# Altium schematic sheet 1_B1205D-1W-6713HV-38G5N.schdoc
size 289 x 200 mm; Name: default297x210; Symbol: default297x210; Device: default297x210; Date: 2025.07.04; Rev: V1.1; Size: "A4"; Id: /; File: B1205D-1W-6713HV-38G5N; Sheet: /; @Page No: 1; @Page Count: 1; @Schematic Name: B1205D-1W-6713HV-38G5N; @Project Name: 全桥隔离电源-B1205D-1W-6713HV-38G5N; @Board Name: B1205D-1W-6713HV-38G5N; @Update Date: 2025-06-24; @Create Time: 13:56:28; @Update Time: 17:11:45; @Page Name: B1205D-1W-6713HV-38G5N; @Create Date: 2025-06-24
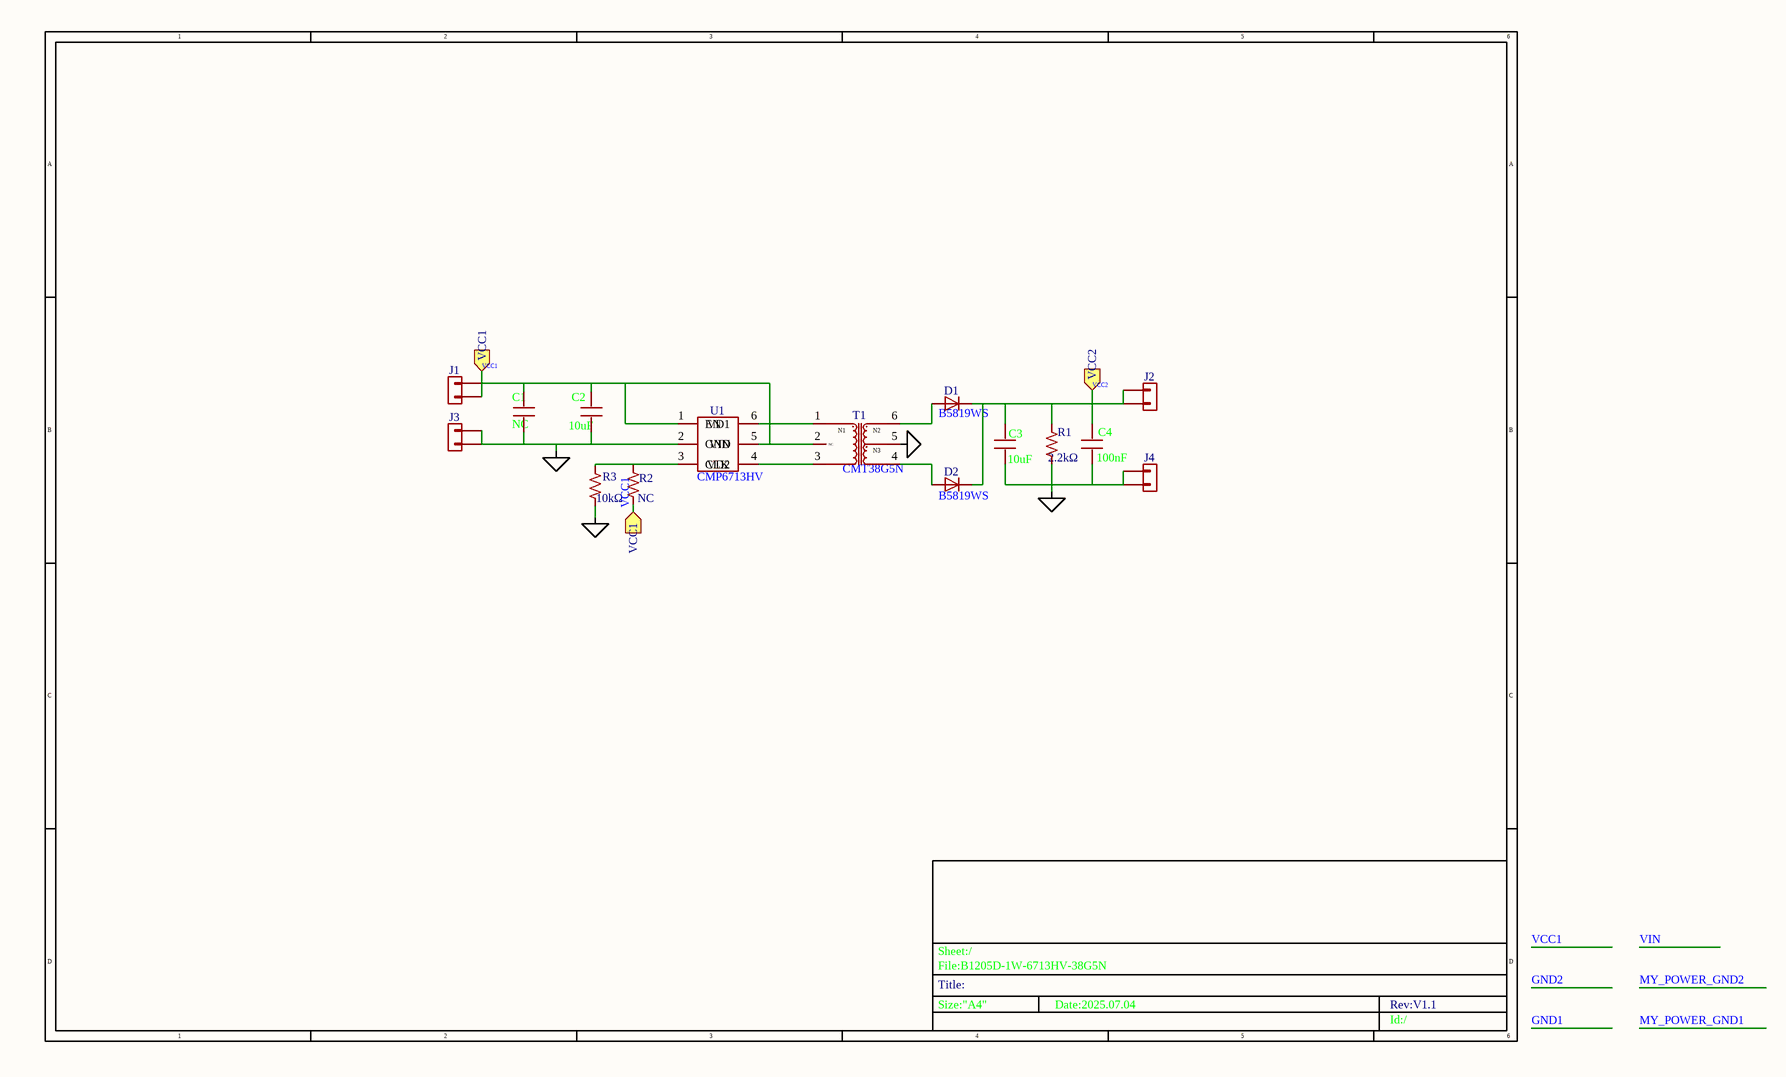
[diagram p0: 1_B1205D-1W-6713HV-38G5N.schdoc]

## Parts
C1  NC  [C0603]
C2  10uF  [C0603]
C3  10uF  [C0603]
C4  100nF  [C0603]
D1  B5819WS  [SOD-323_L1.8-W1.3-LS2.5-RD]
D2  B5819WS  [SOD-323_L1.8-W1.3-LS2.5-RD]
J1  Connector_Generic_Conn_01x02  [Connector_PinHeader_2.54mm:PinHeader_1x02_P2.54mm_Vertical_SMD_Pin1Right]  (value not drawn)
J2  Connector_Generic_Conn_01x02  [Connector_PinHeader_2.54mm:PinHeader_1x02_P2.54mm_Vertical_SMD_Pin1Right]  (value not drawn)
J3  Connector_Generic_Conn_01x02  [Connector_PinHeader_2.54mm:PinHeader_1x02_P2.54mm_Vertical_SMD_Pin1Right]  (value not drawn)
J4  Connector_Generic_Conn_01x02  [Connector_PinHeader_2.54mm:PinHeader_1x02_P2.54mm_Vertical_SMD_Pin1Right]  (value not drawn)
R1  2.2kΩ  [R0603]
R2  NC  [R0603]
R3  10kΩ  [R0603]
T1  CMT38G5N  [MYLibrary:CMT68-38]
U1  CMP6713HV  [MYLibrary:SOT23-6]

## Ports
VCC1 (in), VCC2 (in)

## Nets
GND1: C1.1 C2.1 J3.1 J3.2 R3.2 U1.2(GND)
GND2: C3.1 C4.1 J4.1 J4.2 R1.2 T1.5
VCC1: C1.2 C2.2 J1.1 J1.2 R2.2 T1.2 U1.1(EN) U1.5(VIN) ; port VCC1
VCC2: C3.2 C4.2 D1.1 D2.1 J2.1 J2.2 R1.1 ; port VCC2
NetD1_2: D1.2 T1.6
NetD2_2: D2.2 T1.4
NetR2_1: R2.1 R3.1 U1.3(CLK)
NetT1_1: T1.1 U1.6(VD1)
NetT1_3: T1.3 U1.4(VD2)

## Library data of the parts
C1 = R: Add into BOM: yes; Tolerance: ±10%
C2 = 0603X106M250NT: Manufacturer: FH(风华); Symbol: R; Add into BOM: yes; Tolerance: ±20%; Voltage Rating: 25V; Temperature Coefficient: X5R
C3 = 0603X106K100NT: Manufacturer: FH(风华); Symbol: R; Add into BOM: yes; Tolerance: ±10%; Voltage Rated: 10V; Temperature Coefficient: X5R
C4 = CC0603KRX7R9BB104: Manufacturer: YAGEO(国巨); Symbol: R; Add into BOM: yes; Tolerance: ±10%; Voltage Rating: 50V; Temperature Coefficient: X7R
D1 D2 = B5819WS_C64886: Manufacturer: MDD(辰达半导体); Symbol: My_Library_D; Add into BOM: yes; Diode Configuration: 独立式; Forward Voltage (Vf@If): 900mV@3A; Reverse Voltage (Vr): 40V; Rectified Current: 1A; Reverse Leakage Current (Ir): 1mA@40V
J1-J4 = Connector_Generic_Conn_01x02: Users: REF**; Add into BOM: yes
R1 = RC0603FR-072K2L: Manufacturer: YAGEO(国巨); Symbol: R; Add into BOM: yes; Tolerance: ±1%; Power(Watts): 100mW; Voltage-Supply(Max): 75V; Temperature Coefficient: ±100ppm/℃
R2 = R: Add into BOM: yes; Tolerance: ±1%; Power(Watts): 100mW; Overload Voltage (Max): 75V; Temperature Coefficient: ±100ppm/℃
R3 = RC0603FR-0710KL: Manufacturer: YAGEO(国巨); Symbol: R; Add into BOM: yes; Tolerance: ±1%; Power(Watts): 100mW; Overload Voltage (Max): 75V; Temperature Coefficient: ±100ppm/℃
T1 = CMT38G5N: Manufacturer: coileasy(线易); Symbol: My_Library_CMT38xxxx; Add into BOM: yes
U1 = CMP6713HV: Manufacturer: coileasy(线易); Symbol: MyLibrary_CMP6xxxx; Add into BOM: yes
